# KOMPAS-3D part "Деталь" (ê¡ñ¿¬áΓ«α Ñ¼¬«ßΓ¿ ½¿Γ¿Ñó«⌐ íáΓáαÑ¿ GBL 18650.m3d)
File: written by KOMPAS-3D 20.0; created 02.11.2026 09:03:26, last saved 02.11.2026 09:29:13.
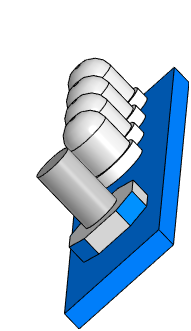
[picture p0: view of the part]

Document properties: Полное имя файла: D:\RicWork\Project-EPS32\box_compas\переключатели и кнопки\Индикатор емкости литиевой батареи GBL 18650.m3d

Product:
- Part/product: Деталь
    Масса: 0.00678464
  - Body: Тело 1
      Масса: 0.00466646

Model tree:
1. Эскиз:1
2. Элемент выдавливания:1
     Расстояние 1 = 1.5
3. Эскиз:2  (with: Элемент выдавливания:1)
4. Элемент выдавливания:2
     Расстояние 1 = 1.5
5. Фаска:1  (with: Элемент выдавливания:2)
     Угол = 45; Длина 1 = 1.5; Длина 2 = 1.5
6. Эскиз:3  (with: Элемент выдавливания:2)
7. Элемент выдавливания:3
     Расстояние 1 = 5
8. Эскиз:4  (with: Элемент выдавливания:1)
9. Элемент выдавливания:4
     Расстояние 1 = 1
10. Эскиз:5  (with: Элемент выдавливания:4)
11. Элемент выдавливания:5
     Расстояние 1 = 4
12. Скругление:1  (with: Элемент выдавливания:5)
     Радиус = 1.5
13. Массив по сетке:3  (with: Элемент выдавливания:4, Эскиз:4, Элемент выдавливания:5, Эскиз:5, Скругление:1, Элемент выдавливания:1)  (4 pattern instances)
     Шаг 1 = 4.7; Угол раствора = 90; Геометрический массив = 128

Referenced files in D:\RicWork\Project-EPS32\box_compas\переключатели и кнопки\: Индикатор емкости литиевой батареи GBL 18650.png
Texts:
  Индикатор емкости литиевой батареи GBL 18650.png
